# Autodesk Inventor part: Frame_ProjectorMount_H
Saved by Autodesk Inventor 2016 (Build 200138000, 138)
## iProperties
Created: 2015-11
Part Number: Frame_ProjectorMount_H
Material: Generic
Document SubType Name: Modeling
Designer: John
Density: 1 g/cm^3
Appearance: Default
Author: John
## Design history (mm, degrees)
feature "Base1"
body "Solid1"
